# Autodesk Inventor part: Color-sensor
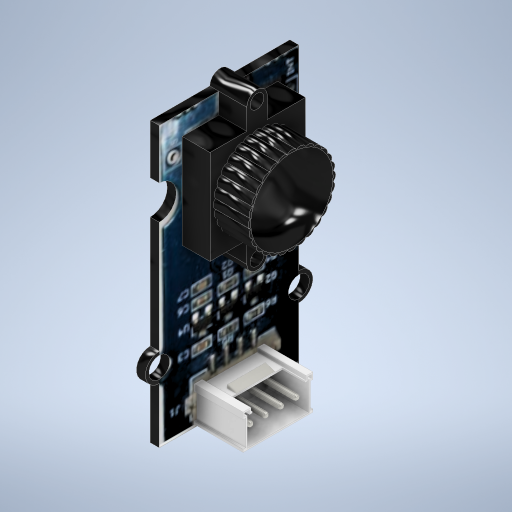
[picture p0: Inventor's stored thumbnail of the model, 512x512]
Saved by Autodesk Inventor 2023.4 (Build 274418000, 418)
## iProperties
Created: 2022-12
Part Number: Color-sensor
Material: Générique
Document SubType Name: Modeling
Designer: ecuenot
Density: 1 g/cm^3
Appearance: Noir
Author: ecuenot
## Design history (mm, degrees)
sketch "Esquisse1" dims "d48" = 3
  geometry: L1 (40, 0)-(40, -20); L2 (0, -20)-(0, 0); L3 (11.5, 0)-(12, 0); L4 (10, 0)-(8, 0); L5 (0, 0)-(8, 0); L6 (11.5, 0)-(40, 0); L7 (40, -20)-(12, -20); L8 (8, -20)-(0, -20); C1 r 1.5 at (10, -20); A1 r 2 centre (10, 0) between (12, 0) and (8, 0); A2 r 2 centre (10, -20) between (8, -20) and (12, -20); 2 further points
  constraints: 16 end point, 5 parallel, 4 point on circle, 3 centre point, 2 coincident, 2 horizontal, 2 perpendicular, 1 horizontal alignment, 2 other
  dimensions: "d0" = 40 distance of L1.end L2.start; "d1" = 20 distance of L1.start L1.end
extrude "Extrusion1" new body sketch "Esquisse1" distance "d9" = 1.3; taper "d10" = 0 deg
sketch "Esquisse15"
  geometry: L1 (0, 0)-(20, 0) reference; L2 (0, 40)-(0, 12) reference; C1 r 2.396 at (10, 0); C2 r 2.429 at (0, 30.425); C3 r 2.696 at (20, 30.425)
  constraints: 3 centre point, 1 midpoint, 1 point on line
extrude "Extrusion11" cut sketch "Esquisse15" distance "d105" = 5; taper "d106" = 0 deg
sketch "Esquisse21"
  geometry: L1 (-20, 40)-(0, 40) reference; C1 r 1 at (-10, 40); C2 r 1.474 at (-10, 40); 5 further points
  constraints: 2 centre point, 1 coincident, 1 midpoint
  dimensions: "d151" = 2 diameter of C1
extrude "Extrusion15" join sketch "Esquisse21" stored distance "d152" = 2; taper "d153" = 0 deg
sketch "Esquisse27"
  geometry: L1 (8.526, 40)-(0, 40) reference; L2 (0, 40)-(19.909, 39.986); L3 (19.909, 39.986)-(19.88, 0); L4 (19.88, 0)-(-0.029, 0.014); L5 (-0.029, 0.014)-(0, 40); 1 further point; 1 other entity
  constraints: 2 other
feature "Décalcomanie3" sketch "Esquisse27"
sketch "Esquisse28"
  geometry: L1 (0.669, -0.155)-(-20.118, -0.155); L2 (-20.118, -0.155)-(-20.118, 40.904); L3 (-20.118, 40.904)-(0.669, 40.904); L4 (0.669, 40.904)-(0.669, -0.155); 1 further point; 1 other entity
  constraints: 2 other
feature "Décalcomanie4" sketch "Esquisse28"
sketch "Esquisse29"
  geometry: L1 (19.5, 39.5)-(0.5, 39.5) reference; L2 (10, 39.5)-(10, 0); L3 (16.953, 37.016)-(3.264, 37.016); L4 (3.264, 37.016)-(3.264, 23.502); L5 (3.264, 23.502)-(16.953, 23.502); L6 (16.953, 23.502)-(16.953, 37.016); L7 (11.474, 37.016)-(8.526, 37.016); L8 (8.526, 37.016)-(8.526, 39.5); L9 (8.526, 39.5)-(11.474, 39.5); L10 (11.474, 39.5)-(11.474, 37.016); L11 (11.474, 39.5)-(11.474, 40); L12 (8.526, 39.5)-(8.526, 40); L13 (11, 40)-(9, 40) reference; L14 (10, 30.259)-(14.396, 30.259); L15 (11.474, 21.018)-(11.474, 23.502); L16 (11.474, 21.018)-(11.474, 20.518); L17 (8.526, 21.018)-(8.526, 20.518); L18 (8.526, 23.502)-(8.526, 21.018); L19 (11.474, 23.502)-(8.526, 23.502); C1 r 5.901 at (10, 30.259); C2 r 1 at (10, 20.518); A1 r 2.396 centre (10, 0) between (12.396, 0) and (7.604, 0) reference; A2 r 1.474 centre (10, 40) between (11.474, 40) and (8.526, 40) reference; A3 r 1.474 centre (10, 40) between (11.474, 40) and (8.526, 40) reference; A4 r 1.474 centre (10, 20.518) between (8.526, 20.518) and (11.474, 20.518); 4 further points
  constraints: 34 end point, 8 symmetric about line, 4 parallel, 3 centre point, 3 horizontal, 3 perpendicular, 3 point on line, 3 vertical, 2 coincident, 2 horizontal alignment, 2 point on circle, 1 midpoint, 6 other
extrude "Extrusion20" join sketch "Esquisse29" distance "d204" = 4; taper "d205" = 0 deg
sketch "Esquisse30"
  geometry: L1 (10, 30.259)-(15.901, 30.259); L2 (15.901, 30.259)-(16.279, 30.259); C1 r 5.901 at (10, 30.259) reference; A1 r 0.858 centre (15.421, 30.259) between (16.279, 30.259) and (15.954, 30.932); A2 r 0.858 centre (15.421, 30.259) between (15.954, 29.586) and (16.279, 30.259); A3 r 0.858 centre (15.285, 31.465) between (15.954, 30.928) and (16.122, 31.656); A4 r 0.858 centre (15.285, 31.465) between (16.122, 31.656) and (15.655, 32.24); A5 r 0.858 centre (14.884, 32.611) between (15.656, 32.236) and (15.658, 32.984); A6 r 0.858 centre (14.884, 32.611) between (15.658, 32.984) and (15.072, 33.449); A7 r 0.858 centre (14.238, 33.639) between (15.074, 33.445) and (14.909, 34.174); A8 r 0.858 centre (14.238, 33.639) between (14.909, 34.174) and (14.235, 34.497); A9 r 0.858 centre (13.38, 34.497) between (14.238, 34.494) and (13.915, 35.168); A10 r 0.858 centre (13.38, 34.497) between (13.915, 35.168) and (13.186, 35.333); A11 r 0.858 centre (12.352, 35.143) between (13.19, 35.331) and (12.725, 35.917); A12 r 0.858 centre (12.352, 35.143) between (12.725, 35.917) and (11.977, 35.915); A13 r 0.858 centre (11.206, 35.544) between (11.981, 35.914) and (11.397, 36.381); A14 r 0.858 centre (11.206, 35.544) between (11.397, 36.381) and (10.669, 36.213); A15 r 0.858 centre (10, 35.68) between (10.673, 36.213) and (10, 36.538); A16 r 0.858 centre (10, 35.68) between (10, 36.538) and (9.327, 36.213); A17 r 0.858 centre (8.794, 35.544) between (9.331, 36.213) and (8.603, 36.381); A18 r 0.858 centre (8.794, 35.544) between (8.603, 36.381) and (8.019, 35.914); A19 r 0.858 centre (7.648, 35.143) between (8.023, 35.915) and (7.275, 35.917); A20 r 0.858 centre (7.648, 35.143) between (7.275, 35.917) and (6.81, 35.331); A21 r 0.858 centre (6.62, 34.497) between (6.814, 35.333) and (6.085, 35.168); A22 r 0.858 centre (6.62, 34.497) between (6.085, 35.168) and (5.762, 34.494); A23 r 0.858 centre (5.762, 33.639) between (5.765, 34.497) and (5.091, 34.174); A24 r 0.858 centre (5.762, 33.639) between (5.091, 34.174) and (4.926, 33.445); A25 r 0.858 centre (5.116, 32.611) between (4.928, 33.449) and (4.342, 32.984); A26 r 0.858 centre (5.116, 32.611) between (4.342, 32.984) and (4.344, 32.236); A27 r 0.858 centre (4.715, 31.465) between (4.345, 32.24) and (3.878, 31.656); A28 r 0.858 centre (4.715, 31.465) between (3.878, 31.656) and (4.046, 30.928); A29 r 0.858 centre (4.579, 30.259) between (4.046, 30.932) and (3.721, 30.259); A30 r 0.858 centre (4.579, 30.259) between (3.721, 30.259) and (4.046, 29.586); A31 r 0.858 centre (4.715, 29.053) between (4.046, 29.59) and (3.878, 28.862); A32 r 0.858 centre (4.715, 29.053) between (3.878, 28.862) and (4.345, 28.278); A33 r 0.858 centre (5.116, 27.907) between (4.344, 28.282) and (4.342, 27.534); A34 r 0.858 centre (5.116, 27.907) between (4.342, 27.534) and (4.928, 27.069); A35 r 0.858 centre (5.762, 26.879) between (4.926, 27.073) and (5.091, 26.344); A36 r 0.858 centre (5.762, 26.879) between (5.091, 26.344) and (5.765, 26.021); A37 r 0.858 centre (6.62, 26.021) between (5.762, 26.024) and (6.085, 25.35); A38 r 0.858 centre (6.62, 26.021) between (6.085, 25.35) and (6.814, 25.185); A39 r 0.858 centre (7.648, 25.375) between (6.81, 25.187) and (7.275, 24.601); A40 r 0.858 centre (7.648, 25.375) between (7.275, 24.601) and (8.023, 24.603); A41 r 0.858 centre (8.794, 24.974) between (8.019, 24.604) and (8.603, 24.137); A42 r 0.858 centre (8.794, 24.974) between (8.603, 24.137) and (9.331, 24.305); A43 r 0.858 centre (10, 24.838) between (9.327, 24.305) and (10, 23.98); A44 r 0.858 centre (10, 24.838) between (10, 23.98) and (10.673, 24.305); A45 r 0.858 centre (11.206, 24.974) between (10.669, 24.305) and (11.397, 24.137); A46 r 0.858 centre (11.206, 24.974) between (11.397, 24.137) and (11.981, 24.604); A47 r 0.858 centre (12.352, 25.375) between (11.977, 24.603) and (12.725, 24.601); A48 r 0.858 centre (12.352, 25.375) between (12.725, 24.601) and (13.19, 25.187); A49 r 0.858 centre (13.38, 26.021) between (13.186, 25.185) and (13.915, 25.35); A50 r 0.858 centre (13.38, 26.021) between (13.915, 25.35) and (14.238, 26.024); A51 r 0.858 centre (14.238, 26.879) between (14.235, 26.021) and (14.909, 26.344); A52 r 0.858 centre (14.238, 26.879) between (14.909, 26.344) and (15.074, 27.073); A53 r 0.858 centre (14.884, 27.907) between (15.072, 27.069) and (15.658, 27.534); A54 r 0.858 centre (14.884, 27.907) between (15.658, 27.534) and (15.656, 28.282); A55 r 0.858 centre (15.285, 29.053) between (15.655, 28.278) and (16.122, 28.862); A56 r 0.858 centre (15.285, 29.053) between (16.122, 28.862) and (15.954, 29.59); 86 further points
  constraints: 112 point on circle, 56 centre point, 4 end point, 2 symmetric about line, 1 coincident, 1 concentric, 1 horizontal, 1 horizontal alignment, 1 point on line, 202 other
  dimensions: "d208" = 360 deg dimension on L1.start A2.centre (derived)
extrude "Extrusion21" join sketch "Esquisse30" distance "d210" = 5; taper "d211" = 0 deg
sketch "Esquisse31"
  geometry: L1 (15, 0.437)-(5, 0.437); L2 (14.043, 4.876)-(6.146, 4.876); L3 (6.146, 4.876)-(6.146, 5.437); L4 (14.043, 5.437)-(14.043, 4.876); L5 (5, 5.437)-(6.146, 5.437); L6 (14.043, 5.437)-(15, 5.437); L7 (15.188, 0.842)-(14.665, 0.842); L8 (14.665, 0.842)-(14.665, 4.504); L9 (14.665, 4.504)-(15.188, 4.504); L10 (5.373, 0.842)-(4.801, 0.842); L11 (4.801, 4.504)-(5.373, 4.504); L12 (5.373, 4.504)-(5.373, 0.842); L13 (5, 0.437)-(5, 0.842); L14 (5, 4.504)-(5, 5.437); L15 (15, 5.437)-(15, 4.504); L16 (15, 0.842)-(15, 0.437); A1 r 2.396 centre (10, 0) between (12.396, 0) and (7.604, 0) reference; 3 further points
  constraints: 32 end point, 9 parallel, 6 point on line, 4 horizontal, 4 perpendicular
  dimensions: "d212" = 5 distance of L1.end L5.start
extrude "Extrusion22" join sketch "Esquisse31" distance "d221" = 7; taper "d222" = 0 deg
sketch "Esquisse33"
  geometry: L1 (5, 5.437)-(5, 4.504) reference; L2 (5, 4.504)-(5.373, 4.504) reference; L3 (5.373, 4.504)-(5.373, 0.842) reference; L4 (5.373, 0.842)-(5, 0.842) reference; L5 (5, 0.842)-(5, 0.437) reference; L6 (5, 0.437)-(15, 0.437) reference; L7 (15, 0.437)-(15, 0.842) reference; L8 (15, 0.842)-(14.665, 0.842) reference; L9 (14.665, 0.842)-(14.665, 4.504) reference; L10 (14.665, 4.504)-(15, 4.504) reference; L11 (15, 4.504)-(15, 5.437) reference; L12 (15, 5.437)-(14.043, 5.437) reference; L13 (14.043, 5.437)-(14.043, 4.876) reference; L14 (14.043, 4.876)-(6.146, 4.876) reference; L15 (6.146, 4.876)-(6.146, 5.437) reference; L16 (6.146, 5.437)-(5, 5.437) reference; L17 (14.443, 0.659)-(5.594, 0.659); L18 (5.594, 0.659)-(5.594, 4.726); L19 (5.594, 4.726)-(5.221, 4.726); L20 (5.221, 4.726)-(5.221, 5.216); L21 (5.221, 5.216)-(5.925, 5.216); L22 (5.925, 5.216)-(5.925, 4.655); L23 (5.925, 4.655)-(14.264, 4.655); L24 (14.264, 4.655)-(14.264, 5.216); L25 (14.264, 5.216)-(14.779, 5.216); L26 (14.779, 5.216)-(14.779, 4.726); L27 (14.779, 4.726)-(14.443, 4.726); L28 (14.443, 4.726)-(14.443, 0.659); 1 further point
  constraints: 24 end point, 11 other
extrude "Extrusion24" cut sketch "Esquisse33" distance "d226" = 6; taper "d227" = 0 deg
sketch "Esquisse34"
  geometry: L1 (8.078, 7.709)-(3.775, 7.709); L2 (3.775, 7.709)-(3.775, 0.199); L3 (3.775, 0.199)-(8.078, 0.199); L4 (8.078, 0.199)-(8.078, 7.709); 1 further point
  constraints: 8 end point, 2 parallel, 1 horizontal, 1 perpendicular
extrude "Extrusion25" cut sketch "Esquisse34" distance "d228" = 2; taper "d229" = 0 deg
node "Plan de construction1"
sketch "Esquisse35"
  geometry: L1 (-3.775, 0)-(3.225, 0) reference; L2 (0.003, 0)-(-1.41, 0.473); L3 (-1.41, 0.473)-(-1.41, 0.026); L4 (-3.775, 0.561)-(3.225, 0.561) reference; L5 (-1.41, 0.026)-(-0.074, 0.026); 1 further point
  constraints: 6 end point, 2 point on line, 1 perpendicular
extrude "Extrusion26" join sketch "Esquisse35" distance "d231" = 5.5; taper "d232" = 0 deg
sketch "Esquisse36" dims "d239" = 10
  geometry: L1 (14.443, 4.726)-(14.443, 0.659) reference; L2 (14.443, 2.692)-(5.594, 2.692); L3 (5.594, 0.659)-(5.594, 4.726) reference; C1 r 0.4 at (13.395, 2.692); C2 r 0.4 at (11.195, 2.692); C3 r 0.4 at (8.995, 2.692); C4 r 0.4 at (6.795, 2.692); 1 further point
  constraints: 4 centre point, 2 end point, 2 midpoint, 1 horizontal, 1 point on line, 6 other
  dimensions: "d233" = 0.8 diameter of C1; "d236" = 2.2 distance of C1.centre C2.centre
extrude "Extrusion27" join sketch "Esquisse36" distance "d241" = 5.5; taper "d242" = 0 deg
fillet "Congé3" dims "d243" = 0.4
node "Solide1"
node "Image8"
node "Image10"
node "Boucle projetée2"
other parameters: "d213" = 5, "d214" = 5, "d230" = 1
